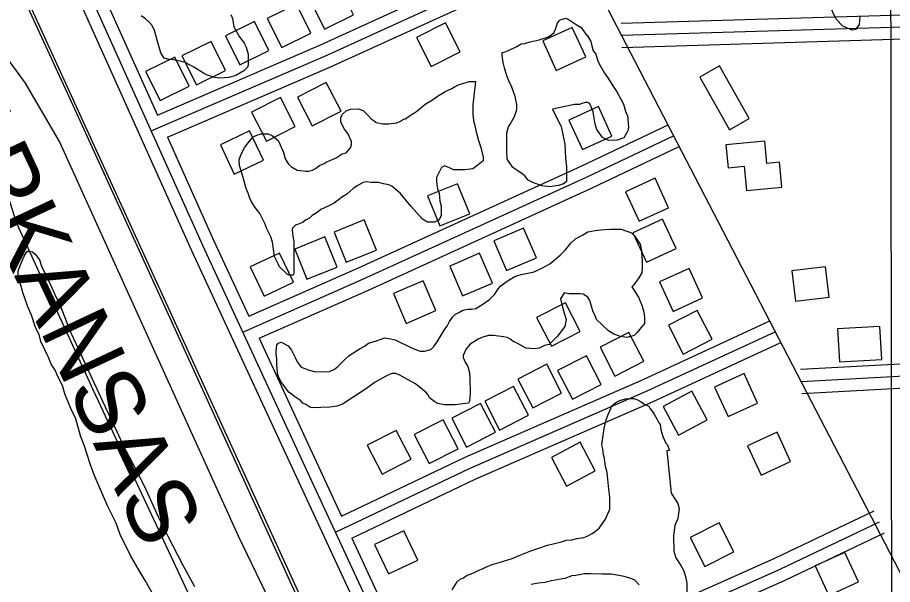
# Model space of a CAD drawing. Extents: x 3313442 to 3351311, y 721974 to 747360.
# Drawn here: x 3326984 to 3328063, y 737395 to 738094 of the extents above; entities that cross this region are included whole.
import ezdxf

# ---------------------------------------------------------------- set-up
doc = ezdxf.new("R2010")
doc.units = 0
for name, color, linetype in [('V-BLDG-OTLN', 7, 'Continuous'), ('V-GRID-MAJR', 7, 'Continuous'), ('V-RAIL-IDEN', 7, 'Continuous'), ('V-RAIL-TRAK', 7, 'Continuous'), ('V-ROAD-CNTR', 7, 'Continuous'), ('V-SITE-VEGE', 7, 'Continuous'), ('V-TOPO-SHOR', 7, 'Continuous')]:
    doc.layers.add(name, color=color, linetype=linetype)

msp = doc.modelspace()

# ---------------------------------------------------------------- linework, layer by layer
at = {"layer": 'V-BLDG-OTLN'}
for points in [[(3327363, 738079.8), (3327398.8, 738097.7), (3327381, 738133.4), (3327345.2, 738115.6)], [(3327310.3, 738057.3), (3327346.1, 738075.2), (3327328.2, 738111), (3327292.4, 738093.1)], [(3327258.6, 738035.9), (3327294.4, 738053.7), (3327276.5, 738089.5), (3327240.8, 738071.7)], [(3327511.9, 738087.8), (3327476.3, 738069.6), (3327494.4, 738034), (3327530.1, 738052.2)], [(3327684.9, 738045.8), (3327668.2, 738082.2), (3327631.9, 738065.5), (3327648.6, 738029.1)], [(3327205, 738011.2), (3327240.8, 738029), (3327223, 738064.8), (3327187.2, 738047)], [(3327160.2, 737991.8), (3327196, 738009.6), (3327178.2, 738045.4), (3327142.4, 738027.6)], [(3327825.5, 738020.8), (3327862.3, 737956), (3327886.6, 737969.9), (3327849.8, 738034.6)], [(3327365.1, 738014.4), (3327329.5, 737996.2), (3327347.7, 737960.6), (3327383.3, 737978.7)], [(3327308.6, 737995.5), (3327273, 737977.4), (3327291.2, 737941.7), (3327326.8, 737959.9)], [(3327717.3, 737948.1), (3327700.6, 737984.5), (3327664.2, 737967.8), (3327680.9, 737931.4)], [(3327234.5, 737937.3), (3327251.7, 737901.2), (3327287.8, 737918.3), (3327270.6, 737954.5)], [(3327883.3, 737880.9), (3327926.8, 737885), (3327923.9, 737915.7), (3327908.4, 737914.2), (3327905.8, 737941.9), (3327857.8, 737937.4), (3327860.5, 737908.9), (3327880.5, 737910.8)], [(3327787.2, 737859.7), (3327770.6, 737896.1), (3327734.2, 737879.4), (3327750.9, 737843)], [(3327504.9, 737837.3), (3327542, 737852.2), (3327527, 737889.3), (3327489.9, 737874.3)], [(3327389.8, 737792.5), (3327426.9, 737807.5), (3327411.9, 737844.6), (3327374.8, 737829.6)], [(3327796.3, 737809.3), (3327779.6, 737845.6), (3327743.2, 737828.9), (3327759.9, 737792.6)], [(3327608.4, 737834.6), (3327571.6, 737818.8), (3327587.4, 737782.1), (3327624.1, 737797.8)], [(3327341.3, 737771.6), (3327378.4, 737786.5), (3327363.5, 737823.6), (3327326.4, 737808.7)], [(3327271.4, 737786.7), (3327288.5, 737750.5), (3327324.7, 737767.7), (3327307.5, 737803.8)], [(3327554.2, 737803.5), (3327517.4, 737787.7), (3327533.2, 737751), (3327569.9, 737766.7)], [(3327943.6, 737744.3), (3327985, 737749.4), (3327980.4, 737786.8), (3327939.1, 737781.7)], [(3327829, 737748.4), (3327812.3, 737784.8), (3327775.9, 737768.1), (3327792.6, 737731.7)], [(3327484.6, 737769.6), (3327447.8, 737753.8), (3327463.6, 737717), (3327500.3, 737732.8)], [(3327642.6, 737688.7), (3327678.2, 737706.9), (3327660, 737742.5), (3327624.4, 737724.3)], [(3327805.2, 737679.1), (3327840.8, 737697.4), (3327822.5, 737733), (3327786.9, 737714.7)], [(3327997.9, 737669.6), (3328049.9, 737672.6), (3328047.5, 737713.3), (3327995.5, 737710.3)], [(3327720.8, 737652), (3327756.4, 737670.3), (3327738.2, 737705.9), (3327702.6, 737687.6)], [(3327668.5, 737623.3), (3327704.1, 737641.5), (3327685.8, 737677.1), (3327650.2, 737658.8)], [(3327619.6, 737612.6), (3327655.2, 737630.9), (3327636.9, 737666.5), (3327601.4, 737648.2)], [(3327896.8, 737618.6), (3327880.1, 737655), (3327843.7, 737638.3), (3327860.4, 737602)], [(3327578.7, 737585.4), (3327614.3, 737603.7), (3327596, 737639.3), (3327560.4, 737621)], [(3327815.9, 737633.3), (3327780.5, 737614.6), (3327799.3, 737579.2), (3327834.6, 737598)], [(3327538.1, 737564.3), (3327573.7, 737582.6), (3327555.4, 737618.2), (3327519.8, 737599.9)], [(3327491.9, 737544.1), (3327527.5, 737562.4), (3327509.2, 737597.9), (3327473.6, 737579.7)], [(3327434, 737531.1), (3327469.6, 737549.3), (3327451.3, 737584.9), (3327415.7, 737566.6)], [(3327937.6, 737546.4), (3327920.9, 737582.7), (3327884.5, 737566), (3327901.2, 737529.7)], [(3327678, 737570.3), (3327642.6, 737551.6), (3327661.4, 737516.2), (3327696.7, 737535)], [(3327831.9, 737417.1), (3327867.6, 737435.1), (3327849.6, 737470.8), (3327813.9, 737452.8)], [(3327424.6, 737444), (3327441.8, 737407.9), (3327477.9, 737425), (3327460.8, 737461.2)], [(3328021.1, 737398.1), (3328004.4, 737434.4), (3327968, 737417.7), (3327984.7, 737381.4)]]:
    msp.add_lwpolyline(points, close=True, dxfattribs=at)
at = {"layer": 'V-GRID-MAJR'}
msp.add_spline([(3328075.1, 727366.3), (3328067.1, 733424.9), (3328059.2, 739486.7), (3328051.3, 745548.5), (3328051.3, 745551.5)], degree=3, dxfattribs=at)
at = {"layer": 'V-RAIL-TRAK'}
msp.add_lwpolyline([(3327407.2, 737206.7), (3327346, 737342.7), (3327255.2, 737542), (3327151.4, 737770.4), (3327055.5, 737980.5), (3327019.5, 738058.9), (3326965.1, 738177.2), (3326868.8, 738389.1), (3326793.1, 738556.9), (3326699.8, 738760.5), (3326584.4, 739013.9)], dxfattribs=at)
at = {"layer": 'V-ROAD-CNTR'}
for points in [[(3327403.8, 738699.8), (3328760.8, 736081.2)], [(3328479, 734877.1), (3327825, 736304.4), (3326995.4, 738119.3), (3326777.2, 738600.5)], [(3326912.1, 738468.3), (3327018.9, 738244.6), (3327212.6, 737813.3), (3327328.5, 737562.7), (3327539.8, 737106.8), (3327748.9, 736642.6), (3327981.7, 736133.7), (3328101.7, 735880.4), (3328340.2, 735352.9), (3328536.1, 734929.8)], [(3326898.6, 738461.8), (3327005.3, 738238.3), (3327198.9, 737807.1), (3327314.9, 737556.4), (3327526.2, 737100.6), (3327735.2, 736636.4), (3327968.1, 736127.4), (3328035.4, 735985.4)], [(3327156.9, 737974), (3327357.3, 738060.4), (3327560.2, 738153.4), (3327663.3, 738200.6)], [(3327149.2, 737954.4), (3327363.4, 738046.7), (3327566.4, 738139.8), (3327669.6, 738187)], [(3327062.8, 738183.6), (3327156.9, 737974)], [(3327169.2, 737946.7), (3327369.4, 738033), (3327572.7, 738126.2), (3327675.8, 738173.3)], [(3328103.5, 738098.3), (3327728.7, 738087)], [(3328103.9, 738083.3), (3327729.1, 738072.1)], [(3328104.4, 738068.3), (3327729.6, 738057.1)], [(3327269.6, 737725.9), (3327405, 737785.5), (3327679.5, 737911.1), (3327786.6, 737962.1)], [(3327262.2, 737706.2), (3327411.1, 737771.8), (3327685.8, 737897.5), (3327793.1, 737948.6)], [(3327169.2, 737946.7), (3327226.2, 737819.6), (3327269.6, 737725.9)], [(3327282.2, 737698.7), (3327417.2, 737758.1), (3327692.2, 737883.9), (3327799.5, 737935)], [(3327383.7, 737479.3), (3327536.2, 737552.1), (3327754.8, 737647.5), (3327912.1, 737720.3)], [(3327376.5, 737459.2), (3327542.4, 737538.5), (3327760.9, 737633.8), (3327918.4, 737706.7)], [(3327282.2, 737698.7), (3327342.2, 737569), (3327383.7, 737479.3)], [(3327396.4, 737452.1), (3327548.6, 737524.8), (3327767.1, 737620.1), (3327924.7, 737693.1)], [(3328126.3, 737669.6), (3327949.6, 737660)], [(3328228.5, 737660.1), (3327950.4, 737645)], [(3328229.4, 737645.1), (3327951.2, 737630)], [(3327495.3, 737238.6), (3327699, 737329.6), (3327918.2, 737427.3), (3328040.5, 737485.7)], [(3327487.9, 737218.9), (3327705.1, 737315.9), (3327924.5, 737413.7), (3328047, 737472.2)], [(3327396.4, 737452.1), (3327495.3, 737238.6)], [(3327507.9, 737211.4), (3327711.2, 737302.2), (3327930.8, 737400), (3328053.4, 737458.7)]]:
    msp.add_lwpolyline(points, dxfattribs=at)
at = {"layer": 'V-SITE-VEGE'}
for points in [[(3328023.1, 738095.5), (3328021.9, 738085.7), (3328017.7, 738079.5), (3328013.4, 738078.9), (3328001.8, 738083.7), (3327993.8, 738092.2), (3327985, 738110.5)], [(3327258.1, 738070.6), (3327263.7, 738062.7), (3327266.2, 738057.8), (3327268.7, 738049.3), (3327268.8, 738037.7), (3327268.2, 738033.4), (3327263.3, 738028.5), (3327253.6, 738022.9), (3327245.1, 738020.4), (3327233.4, 738019.7), (3327227.9, 738020.2), (3327217.5, 738023.8), (3327213.8, 738025.6), (3327202.8, 738032.9), (3327191.1, 738038.9), (3327185, 738040.7), (3327174.5, 738042.4), (3327169.7, 738043), (3327165.4, 738044.2), (3327161, 738050.9), (3327157.9, 738061.9), (3327155.4, 738071), (3327153.5, 738078.3), (3327150.4, 738084.4), (3327147.3, 738088.1), (3327142.3, 738092.9), (3327136.8, 738096.6)], [(3327247.5, 738098.1), (3327249.4, 738093.2), (3327251.3, 738082.8), (3327258.1, 738070.6)], [(3327362.7, 737914.3), (3327365.1, 737916.1), (3327377.3, 737921.1), (3327384.6, 737926.1), (3327389.5, 737927.3), (3327391.9, 737930.4), (3327395, 737933.5), (3327396.2, 737937.2), (3327396.1, 737941.5), (3327391.8, 737951.2), (3327387.4, 737956.7), (3327384.3, 737962.8), (3327383.1, 737965.8), (3327383.1, 737970.7), (3327384.9, 737975), (3327389.7, 737979.3), (3327395.2, 737981.2), (3327405, 737981.9), (3327410.5, 737979.5), (3327416.7, 737973.4), (3327420.4, 737969.2), (3327424.1, 737966.8), (3327426.5, 737964.9), (3327434.5, 737963.2), (3327441.8, 737963.2), (3327452.2, 737964.5), (3327456.5, 737966.4), (3327460.1, 737968.9), (3327462.6, 737969.5), (3327466.2, 737972), (3327471.1, 737975.1), (3327475.3, 737977.6), (3327481.4, 737982.5), (3327486.9, 737987.5), (3327496, 737993), (3327502.1, 737997.4), (3327508.2, 738001.1), (3327511.8, 738002.9), (3327519.8, 738006.7), (3327524, 738009.2), (3327528.9, 738011.6), (3327537.4, 738014.2), (3327541.1, 738015.4), (3327549, 738015.5), (3327545.6, 737986.7)], [(3327545.6, 737986.7), (3327545.7, 737975.7), (3327546.4, 737967.1), (3327548.2, 737961), (3327549.5, 737954.9), (3327552.7, 737942.7), (3327555.8, 737934.2), (3327558.4, 737922), (3327558.4, 737917.7), (3327550.5, 737910.9), (3327545.6, 737907.8), (3327535.8, 737906.5), (3327521.8, 737906.4), (3327516.9, 737908.8), (3327510.7, 737911.2), (3327507.1, 737909.3), (3327501.1, 737897.1), (3327501.1, 737891.6), (3327502.4, 737882.4), (3327504.3, 737877.5), (3327505, 737867.7), (3327506.9, 737861.6), (3327506.9, 737850.6), (3327505.1, 737846.3), (3327503.3, 737844.5), (3327498.4, 737842), (3327489.9, 737841.9), (3327483.7, 737845.5), (3327469.6, 737861.3), (3327463.4, 737868.6), (3327456, 737877.7), (3327446.1, 737886.2), (3327442.4, 737888), (3327435.7, 737889.2), (3327429.6, 737891), (3327420.4, 737890.9), (3327414.9, 737891.5), (3327410.6, 737890.8), (3327403.9, 737887.1), (3327398.4, 737883.4), (3327390.5, 737876.6), (3327383.8, 737872.3), (3327374.7, 737865.5), (3327367.4, 737861.7), (3327358.3, 737857.4), (3327354, 737853.7), (3327347.9, 737850), (3327344.3, 737846.9), (3327339.4, 737844.4), (3327335.8, 737841.3), (3327329.7, 737838.8), (3327327.2, 737838.2), (3327323.6, 737834.5), (3327323, 737832), (3327323.7, 737824.7), (3327325, 737818), (3327325.3, 737778.2), (3327324.1, 737776.4), (3327319.8, 737776.3), (3327317.3, 737777.5), (3327307.5, 737786.6), (3327305.6, 737790.3), (3327301.3, 737799.4), (3327300.6, 737805.5), (3327298.7, 737817.1), (3327296.8, 737823.9), (3327291.8, 737833.6), (3327289.3, 737840.3), (3327283.1, 737852.5), (3327277.5, 737859.8), (3327272.6, 737867.7), (3327270.7, 737871.4), (3327268.8, 737877.5), (3327266.3, 737883.5), (3327262.6, 737897), (3327258.2, 737911.6), (3327257.5, 737918.9), (3327259.3, 737923.9), (3327262.3, 737930), (3327264.7, 737934.3), (3327268.9, 737939.8), (3327272.6, 737944.1), (3327275, 737947.2), (3327279.3, 737949.1), (3327284.8, 737951), (3327293.3, 737951), (3327298.8, 737948.6), (3327305.6, 737942.6), (3327308.1, 737937.1), (3327312.5, 737927.9), (3327314.4, 737920), (3327318.7, 737913.3), (3327322.4, 737910.3), (3327329.1, 737906.1), (3327333.4, 737905.5), (3327339.6, 737904.9), (3327343.2, 737905), (3327348.1, 737906.2), (3327351.8, 737908.1), (3327356.6, 737911.8), (3327362.7, 737914.3)], [(3327514.2, 737713.7), (3327517.2, 737719.2), (3327520.8, 737724.8), (3327524.4, 737728.5), (3327529.3, 737730.9), (3327533.6, 737733.4), (3327539.7, 737734.7), (3327544, 737734.7), (3327549.5, 737735.4), (3327556.8, 737739.7), (3327566.5, 737746.5), (3327572.6, 737752.7), (3327577.4, 737760.1), (3327580.4, 737763.2), (3327585.3, 737766.9), (3327589.5, 737770), (3327597.4, 737774.9), (3327599.9, 737775.5), (3327605.4, 737777.4), (3327615.8, 737779.3), (3327621.3, 737780.6), (3327631.6, 737785.6), (3327640.7, 737790.5), (3327653.5, 737801), (3327660.2, 737807.8), (3327666.8, 737815.8), (3327672.3, 737821.4), (3327681.4, 737826.3), (3327687.5, 737830.1), (3327696.7, 737831.4), (3327703.4, 737832.6), (3327715.6, 737833.3), (3327728.5, 737833.4), (3327741.3, 737828.7), (3327745.7, 737824.4), (3327751.9, 737814.7), (3327753.8, 737806.1), (3327754.5, 737793.9), (3327754.5, 737787.2), (3327754, 737779.2), (3327750.4, 737773.1), (3327744.3, 737764.5), (3327741.9, 737762), (3327749.9, 737749.2), (3327754.3, 737739.5), (3327756.8, 737730.9), (3327757.5, 737724.8), (3327757.5, 737716.9), (3327753.3, 737711.9), (3327748.4, 737705.8), (3327744.8, 737702.1), (3327735.7, 737699.6), (3327727.7, 737700.7), (3327719.7, 737703.7), (3327713, 737708), (3327698.2, 737721.9), (3327697.5, 737724.3), (3327693.8, 737732.3), (3327690, 737745.1), (3327687.6, 737749.3), (3327682, 737753), (3327677.7, 737753.5), (3327664.3, 737753.4), (3327658.2, 737754.6), (3327653.9, 737747.2)], [(3327150.6, 737384.6), (3327141.9, 737399.8), (3327134.5, 737412), (3327123.9, 737430.8), (3327110.9, 737456.4), (3327105.9, 737470.4), (3327095.9, 737491.2), (3327089.1, 737506.4), (3327079.1, 737530.2), (3327074.1, 737543.6), (3327067.2, 737565.5), (3327062.2, 737578.3), (3327056.5, 737599.1), (3327050.3, 737611.9), (3327042.8, 737630.2), (3327039.7, 737640.5), (3327034.1, 737651.5), (3327031, 737659.4), (3327026, 737666.7), (3327022.9, 737674), (3327013, 737694.7), (3327011.1, 737703.3), (3327006.7, 737711.8), (3327001.7, 737727.1), (3326997.3, 737737.4), (3326991.1, 737755.1), (3326988.5, 737764.3), (3326985.4, 737774), (3326985.4, 737781.4), (3326986.5, 737785), (3326988.9, 737791.2), (3326992.5, 737799.8), (3326995, 737804.1), (3326996.8, 737805.9), (3326999.2, 737805.9), (3327002.9, 737805.3), (3327006, 737802.3)], [(3327006, 737802.3), (3327011.5, 737795.6), (3327014, 737787.7), (3327025.2, 737764.6), (3327032.7, 737748.1), (3327035.2, 737743.2), (3327050.2, 737705.4), (3327062.6, 737679.2), (3327070.7, 737661), (3327092.5, 737614), (3327106.8, 737583.6), (3327115.5, 737564.7), (3327132.3, 737533), (3327142.9, 737511.1), (3327158.4, 737477.6), (3327169.6, 737454.4), (3327188.2, 737418.5), (3327202.5, 737392.3)], [(3327653.9, 737747.2), (3327657.1, 737733.8), (3327660.9, 737721.6), (3327659.1, 737713), (3327650, 737701.3), (3327639.7, 737690.9), (3327634.2, 737689.6), (3327627.5, 737686.5), (3327621.4, 737685.8), (3327611.6, 737686.3), (3327606.1, 737689.4), (3327598.7, 737693.6), (3327595.6, 737694.8), (3327591.3, 737697.8), (3327588.3, 737699.6), (3327583.4, 737700.2), (3327571.1, 737701.9), (3327565, 737701.9), (3327558.3, 737700), (3327552.2, 737697.5), (3327542.5, 737691.3), (3327537.6, 737685.8), (3327534, 737677.2), (3327534, 737674.7), (3327536.5, 737669.2), (3327539.6, 737663.8), (3327541.5, 737655.8), (3327542.2, 737649.7), (3327542.3, 737630.8), (3327541.8, 737621), (3327540.6, 737618.5), (3327533.9, 737617.8), (3327524.1, 737616.5), (3327510.7, 737616.4), (3327502.7, 737618.2), (3327499, 737620), (3327492.9, 737624.8), (3327490.4, 737629.1), (3327487.9, 737632.1), (3327484.2, 737635.2), (3327475, 737642.4), (3327465.1, 737647.9), (3327455.9, 737653.3), (3327451, 737655.1), (3327446.1, 737655), (3327440, 737652.6), (3327425.4, 737644.5), (3327413.3, 737635.8), (3327394.4, 737623.4), (3327385.3, 737617.3), (3327378, 737614.8), (3327369.4, 737613.5), (3327358.4, 737613.4), (3327350.5, 737612.7), (3327345.6, 737613.3), (3327340.6, 737616.3), (3327336.3, 737618.7), (3327333.3, 737621.7), (3327325.9, 737626.6), (3327319.1, 737632), (3327309.8, 737644.2), (3327308.6, 737646), (3327306.1, 737651.5), (3327304.9, 737655.7), (3327304.2, 737666.8), (3327304.1, 737673.5), (3327303.5, 737679), (3327303.4, 737683.3), (3327304, 737690), (3327305.8, 737692.4), (3327309.4, 737693.7), (3327318, 737689.5), (3327322.4, 737684), (3327326.7, 737674.9), (3327329.2, 737669.4), (3327332.9, 737664.5), (3327335.4, 737662.7), (3327344, 737659.1), (3327351.9, 737657.3), (3327369.1, 737657.5), (3327375.1, 737660.6), (3327379.4, 737663.7), (3327387.3, 737671.7), (3327393.4, 737677.3), (3327406.7, 737685.9), (3327412.2, 737689), (3327417.1, 737692.7), (3327426.9, 737695.3), (3327431.7, 737697.1), (3327437.2, 737699), (3327442.1, 737698.4), (3327450.1, 737696.7), (3327471, 737686.4), (3327480.8, 737682.8), (3327486.3, 737682.9), (3327494.2, 737684.8), (3327497.8, 737688.5), (3327502.7, 737695.3), (3327505.7, 737700.2), (3327511.1, 737710), (3327514.2, 737713.7)], [(3327520.4, 737388.4), (3327526.5, 737398.2), (3327530.1, 737401.3), (3327534.4, 737403.2), (3327538.6, 737406.3), (3327542.9, 737407.5), (3327549, 737410.6), (3327561.8, 737416.3), (3327569.7, 737419.4), (3327578.3, 737421.9), (3327594.1, 737426.9), (3327602.7, 737430.6), (3327617.3, 737436.3), (3327625.8, 737439.4), (3327638, 737443.2), (3327644.7, 737445), (3327655.1, 737447.6), (3327661.2, 737449.5), (3327667.9, 737450.1), (3327674, 737451.4), (3327682.6, 737452.7), (3327686.9, 737454.6), (3327693, 737457.7), (3327697.2, 737460.8), (3327701.5, 737464.5), (3327709.3, 737475.5), (3327714.7, 737487.8), (3327714.6, 737502.5), (3327713.3, 737512.3), (3327711.3, 737533), (3327709.4, 737540.4), (3327708.1, 737550.1), (3327706.8, 737555), (3327706.2, 737562.3), (3327704.9, 737567.2), (3327707.8, 737587.4), (3327710.2, 737597.9), (3327712.6, 737604.6), (3327716.2, 737612.6), (3327716.8, 737615), (3327722.2, 737619.4), (3327727.1, 737621.8), (3327733.8, 737623.7), (3327738.7, 737624.4), (3327744.2, 737624.4), (3327747.9, 737623.2), (3327753.4, 737620.2), (3327756.5, 737617.8), (3327762.6, 737614.8), (3327764.5, 737611.7), (3327767, 737608.7), (3327769.4, 737605.1)], [(3327769.4, 737605.1), (3327773.2, 737598.4), (3327775, 737594.1), (3327776.9, 737592.3), (3327777.5, 737586.2), (3327780.1, 737577.6), (3327783.8, 737569.1), (3327785.6, 737567.3), (3327787.5, 737562.4), (3327788.1, 737560), (3327785.1, 737559.9), (3327790.4, 737507.4)], [(3327790.4, 737507.4), (3327798.5, 737494.6), (3327800.3, 737488.5), (3327798.6, 737476.3), (3327795, 737467.7), (3327793.3, 737454.8), (3327793.4, 737435.8), (3327795.9, 737427.9), (3327802.1, 737418.2), (3327805.9, 737411.5), (3327808.4, 737402.9), (3327809.6, 737396.2), (3327809.8, 737380.3)], [(3327750.9, 737394.5), (3327745.4, 737400), (3327740.5, 737402.4), (3327732.5, 737404.8), (3327716.6, 737407.7), (3327705.6, 737407.6), (3327690.9, 737408.1), (3327683, 737408.1), (3327672.6, 737406.1), (3327667.7, 737405.5), (3327659.2, 737402.4), (3327651.8, 737401.1), (3327642.7, 737399.2), (3327634.7, 737397.3), (3327626.8, 737396.6), (3327617.6, 737394.7)]]:
    msp.add_lwpolyline(points, dxfattribs=at)
msp.add_lwpolyline([(3327644.1, 737981.4), (3327652.2, 737964.3), (3327654.7, 737960.1), (3327659.1, 737938.1), (3327659.9, 737921), (3327661.2, 737910), (3327661.3, 737892.2), (3327657.7, 737889.1), (3327651.6, 737887.3), (3327640.6, 737885.3), (3327630.8, 737886.5), (3327619.8, 737890.7), (3327614.2, 737893.7), (3327609.9, 737899.2), (3327606.8, 737901.6), (3327601.3, 737905.2), (3327595.1, 737909.4), (3327588.3, 737919.8), (3327587.6, 737928.9), (3327587.5, 737951.6), (3327589.8, 737959.5), (3327591.7, 737962.6), (3327597.1, 737972.4), (3327600.1, 737981), (3327600, 737987.1), (3327598.1, 737996.9), (3327593.7, 738008.5), (3327590, 738016.4), (3327587.5, 738022.5), (3327585, 738032.3), (3327583.1, 738039), (3327581.8, 738047.5), (3327581.8, 738051.2), (3327586.7, 738052.5), (3327591.5, 738054.3), (3327600.1, 738058.7), (3327605.5, 738061.8), (3327609.8, 738062.4), (3327616.5, 738064.3), (3327627.5, 738066.9), (3327639.1, 738070.6), (3327645.8, 738075.6), (3327647.6, 738079.9), (3327650, 738087.2), (3327651.8, 738089.7), (3327653.6, 738091.5), (3327660.3, 738093.4), (3327664.6, 738091.6), (3327673.2, 738085.6), (3327679.4, 738082), (3327684.9, 738074), (3327686.8, 738072.8), (3327691.1, 738064.9), (3327692.4, 738059.4), (3327694.3, 738053.3), (3327697.4, 738049.1), (3327699.9, 738040.5), (3327703, 738034.4), (3327708, 738025.9), (3327712.3, 738019.8), (3327719.1, 738008.9), (3327723.4, 738002.8), (3327727.8, 737994.3), (3327731.5, 737987.6), (3327734.6, 737977.2), (3327736.5, 737973.6), (3327737.8, 737958.9), (3327736.7, 737954.6), (3327731.8, 737946), (3327723.9, 737942.9), (3327712.9, 737942.8), (3327705.5, 737946.4), (3327698.7, 737956.1), (3327696.8, 737962.8), (3327694.9, 737972.6), (3327694.3, 737978.1), (3327691.8, 737984.2), (3327689.9, 737987.9), (3327687.5, 737989.7), (3327684.4, 737989.7), (3327680.1, 737988.4), (3327677.1, 737987.1), (3327671, 737987.1)], close=True, dxfattribs=at)
at = {"layer": 'V-TOPO-SHOR'}
msp.add_line((3326994.1, 738013.4), (3326944.1, 738081.7), dxfattribs=at)
for points in [[(3326893.2, 738037.7), (3326914.2, 738018.9), (3326931.9, 737987), (3326956.2, 737924.9), (3326983.1, 737840.7), (3327077.7, 737634.5), (3327399.9, 736945.4)], [(3327482.7, 736986), (3327256.9, 737454.3), (3327036.3, 737941.4), (3326994.1, 738013.4)]]:
    msp.add_lwpolyline(points, dxfattribs=at)

# ---------------------------------------------------------------- texts
at = {"layer": 'V-RAIL-IDEN'}
msp.add_text('ARKANSAS', height=83, rotation=295.1617, dxfattribs=at).set_placement((3326882.9, 737982.7))

doc.saveas('drawing.dxf')
